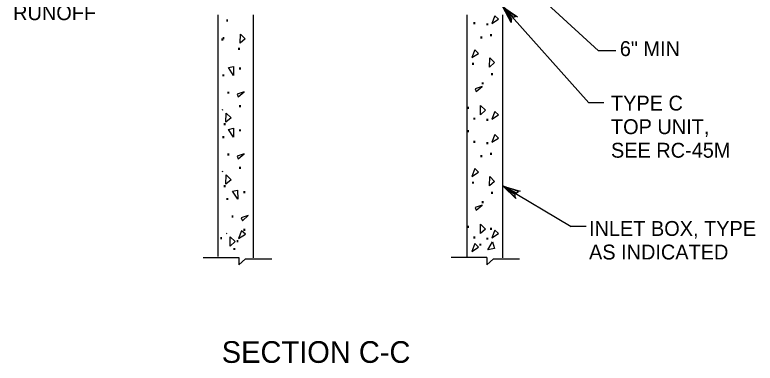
# Model space of a CAD drawing. Extents: x 636183 to 639890, y 299162 to 300538.
# Drawn here: x 637670.6 to 637819.7, y 299781.7 to 299851.9 of the extents above; entities that cross this region are included whole.
import ezdxf

# ---------------------------------------------------------------- set-up
doc = ezdxf.new("R2010")
doc.units = 0
doc.layers.add('Default', color=7, linetype='Continuous')

msp = doc.modelspace()

# ---------------------------------------------------------------- linework, layer by layer
at = {"layer": 'Default'}
for p, q in [((637768.93, 299853.57), (637786.19, 299834.21)), ((637711.5, 299803.24), (637711.5, 299851.94)), ((637718.66, 299802.96), (637718.66, 299851.94)), ((637761.65, 299803.24), (637761.65, 299851.94)), ((637791.6, 299844.69), (637788.11, 299844.69)), ((637789.19, 299834.21), (637786.19, 299834.21)), ((637712.46, 299832.82), (637712.29, 299832.76)), ((637712.46, 299820.35), (637712.29, 299820.29)), ((637768.88, 299817.45), (637782.63, 299809.29)), ((637785.63, 299809.29), (637782.63, 299809.29)), ((637713.29, 299807.88), (637713.13, 299807.83)), ((637708.52, 299803.05), (637715.68, 299803.05)), ((637715.68, 299803.05), (637715.68, 299801.56)), ((637715.68, 299801.56), (637717.06, 299802.77)), ((637717.06, 299802.77), (637722.31, 299802.77)), ((637765.61, 299803.05), (637765.61, 299801.56)), ((637765.61, 299801.56), (637766.98, 299802.77)), ((637766.98, 299802.77), (637772.24, 299802.77))]:
    msp.add_line(p, q, dxfattribs=at)
for points in [[(637791.6, 299844.69), (637788.11, 299844.69), (637774.68, 299857.02)], [(637770.51, 299850.72), (637770.52, 299850.37), (637768.84, 299853.56), (637770.51, 299850.72), (637770.66, 299851.12), (637768.84, 299853.56), (637771.04, 299851.47), (637771.44, 299851.58), (637768.84, 299853.56), (637771.82, 299851.54), (637771.44, 299851.58)], [(637768.81, 299851.94), (637768.81, 299802.96)], [(637771.35, 299815.23), (637771.47, 299814.9), (637768.9, 299817.44), (637771.35, 299815.23), (637771.37, 299815.65), (637768.9, 299817.44), (637771.64, 299816.1), (637771.99, 299816.33), (637768.9, 299817.44), (637772.36, 299816.41), (637771.99, 299816.33)], [(637765.61, 299803.05), (637758.45, 299803.05)]]:
    msp.add_lwpolyline(points, dxfattribs=at)
for points in [[(637766.64, 299850.18), (637768.01, 299851.04), (637767.24, 299851.74)], [(637766.64, 299850.18), (637768.01, 299851.04), (637767.24, 299851.74)], [(637716.98, 299847.11), (637715.95, 299846.21), (637716, 299848.07)], [(637762.6, 299843.31), (637763.98, 299844.17), (637763.2, 299844.87)], [(637762.6, 299843.31), (637763.98, 299844.17), (637763.2, 299844.87)], [(637767.19, 299842.3), (637766.16, 299841.4), (637766.21, 299843.26)], [(637767.19, 299842.3), (637766.16, 299841.4), (637766.21, 299843.26)], [(637713.6, 299841.32), (637714.6, 299841.55), (637714.63, 299839.73)], [(637715.34, 299835.94), (637715.58, 299835.39), (637716.76, 299836.41)], [(637763.28, 299837.03), (637763.52, 299836.48), (637764.7, 299837.5)], [(637763.28, 299837.03), (637763.52, 299836.48), (637764.7, 299837.5)], [(637765.37, 299832.7), (637764.34, 299831.81), (637764.38, 299833.67)], [(637765.37, 299832.7), (637764.34, 299831.81), (637764.38, 299833.67)], [(637714.12, 299831.18), (637713.09, 299830.29), (637713.13, 299832.14)], [(637766.64, 299830.92), (637768.01, 299831.78), (637767.24, 299832.48)], [(637766.64, 299830.92), (637768.01, 299831.78), (637767.24, 299832.48)], [(637713.6, 299828.86), (637714.6, 299829.09), (637714.63, 299827.26)], [(637766.64, 299826.25), (637768.01, 299827.11), (637767.24, 299827.81)], [(637766.64, 299826.25), (637768.01, 299827.11), (637767.24, 299827.81)], [(637766.64, 299826.25), (637768.01, 299827.11), (637767.24, 299827.81)], [(637715.34, 299823.48), (637715.58, 299822.93), (637716.76, 299823.95)], [(637762.6, 299819.38), (637763.98, 299820.24), (637763.2, 299820.94)], [(637762.6, 299819.38), (637763.98, 299820.24), (637763.2, 299820.94)], [(637762.6, 299819.38), (637763.98, 299820.24), (637763.2, 299820.94)], [(637714.12, 299818.72), (637713.09, 299817.82), (637713.13, 299819.68)], [(637767.19, 299818.37), (637766.16, 299817.47), (637766.21, 299819.33)], [(637767.19, 299818.37), (637766.16, 299817.47), (637766.21, 299819.33)], [(637767.19, 299818.37), (637766.16, 299817.47), (637766.21, 299819.33)], [(637714.44, 299816.39), (637715.43, 299816.62), (637715.47, 299814.8)], [(637763.28, 299813.1), (637763.52, 299812.55), (637764.7, 299813.57)], [(637763.28, 299813.1), (637763.52, 299812.55), (637764.7, 299813.57)], [(637763.28, 299813.1), (637763.52, 299812.55), (637764.7, 299813.57)], [(637716.18, 299811.01), (637716.42, 299810.46), (637717.6, 299811.48)], [(637765.37, 299808.77), (637764.34, 299807.88), (637764.38, 299809.74)], [(637765.37, 299808.77), (637764.34, 299807.88), (637764.38, 299809.74)], [(637765.37, 299808.77), (637764.34, 299807.88), (637764.38, 299809.74)], [(637715.65, 299806.86), (637717.02, 299807.72), (637716.25, 299808.42)], [(637766.64, 299806.99), (637768.01, 299807.85), (637767.24, 299808.55)], [(637766.64, 299806.99), (637768.01, 299807.85), (637767.24, 299808.55)], [(637766.64, 299806.99), (637768.01, 299807.85), (637767.24, 299808.55)], [(637714.96, 299806.25), (637713.92, 299805.35), (637713.97, 299807.21)], [(637762.6, 299804.27), (637763.98, 299805.13), (637763.2, 299805.83)], [(637767.18, 299804.86), (637765.84, 299804.59), (637766.81, 299806.19)]]:
    msp.add_lwpolyline(points, close=True, dxfattribs=at)

# ---------------------------------------------------------------- texts
for s, height, p in [('RUNOFF', 2.998, (637670.24, 299850.87)), ('6" MIN', 2.998, (637792.42, 299843.63)), ('TYPE C', 2.998, (637790.64, 299832.65)), ('TOP UNIT,', 2.998, (637790.64, 299827.9)), ('SEE RC-45M', 2.998, (637790.64, 299823.15)), ('INLET BOX, TYPE', 2.998, (637786.22, 299807.39)), ('AS INDICATED', 2.998, (637786.22, 299802.64)), ('SECTION C-C', 4.3721, (637712.25, 299781.81))]:
    msp.add_text(s, height=height, dxfattribs=at).set_placement(p)
for p in [(637713.89, 299851.04), (637763.68, 299850.5), (637763.68, 299850.5), (637766.28, 299850.25), (637766.28, 299850.25), (637767.02, 299848.09), (637767.02, 299848.09), (637712.91, 299847.21), (637713.15, 299847.44), (637765.09, 299847.62), (637765.09, 299847.62), (637716.26, 299845.29), (637763.39, 299842.28), (637763.39, 299842.28), (637716.49, 299841.36), (637713.11, 299839.98), (637767.22, 299840.22), (637767.22, 299840.22), (637765.34, 299838.36), (637765.34, 299838.36), (637714.12, 299836.48), (637716.49, 299833.78), (637762.41, 299833.4), (637762.41, 299833.4), (637763.68, 299831.24), (637763.68, 299831.24), (637766.28, 299830.99), (637766.28, 299830.99), (637713.39, 299830.11), (637716.49, 299828.89), (637762.41, 299828.72), (637762.41, 299828.72), (637762.41, 299828.72), (637713.11, 299827.52), (637763.68, 299826.57), (637763.68, 299826.57), (637763.68, 299826.57), (637766.28, 299826.32), (637766.28, 299826.32), (637766.28, 299826.32), (637767.02, 299824.16), (637767.02, 299824.16), (637767.02, 299824.16), (637714.12, 299824.01), (637765.09, 299823.69), (637765.09, 299823.69), (637765.09, 299823.69), (637716.49, 299821.31), (637763.39, 299818.35), (637763.39, 299818.35), (637763.39, 299818.35), (637713.39, 299817.64), (637717.33, 299816.42), (637767.22, 299816.29), (637767.22, 299816.29), (637767.22, 299816.29), (637713.94, 299815.05), (637765.34, 299814.43), (637765.34, 299814.43), (637765.34, 299814.43), (637714.96, 299811.54), (637762.41, 299809.47), (637762.41, 299809.47), (637762.41, 299809.47), (637717.33, 299808.84), (637767.02, 299809.05), (637712.69, 299807.19), (637715.98, 299806.57), (637763.68, 299807.31), (637763.68, 299807.31), (637763.68, 299807.31), (637766.28, 299807.06), (637766.28, 299807.06), (637766.28, 299807.06), (637715.33, 299804.98), (637764.88, 299805.86)]:
    msp.add_text('.', height=2.94, rotation=180, dxfattribs=at).set_placement(p)

doc.saveas('drawing.dxf')
